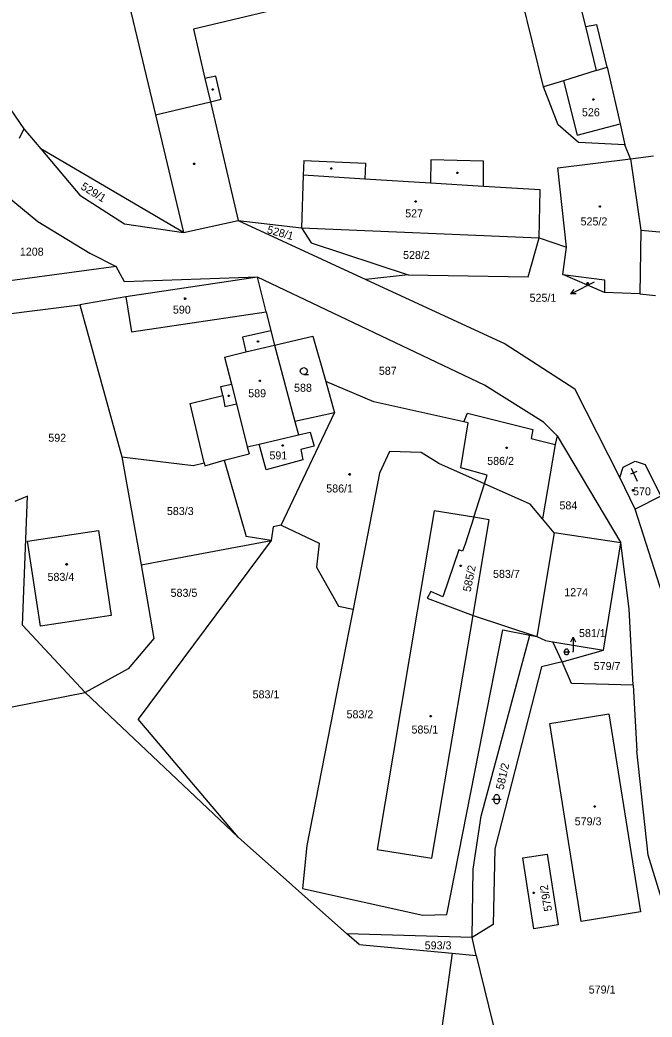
# Model space of a CAD drawing. Extents: x -812394 to -807601, y -1013097 to -1009266.
# Drawn here: x -809217.6 to -809083.2, y -1011807.5 to -1011595.7 of the extents above; entities that cross this region are included whole.
import ezdxf

# ---------------------------------------------------------------- set-up
doc = ezdxf.new("R2010")
doc.units = 0
for name, color, linetype in [('Default', 7, 'Continuous'), ('KN_HRANICE', 7, 'Continuous'), ('KN_KULTURY', 7, 'Continuous'), ('KN_PARCELY', 7, 'Continuous'), ('KN_SLUCKY', 7, 'Continuous')]:
    doc.layers.add(name, color=color, linetype=linetype)

# ---------------------------------------------------------------- blocks, each defined once
blk = doc.blocks.new('10292')
at = {"layer": 'Default'}
blk.add_line((0, 3), (0, 0), dxfattribs=at)
blk.add_lwpolyline([(-0.5, 2), (0, 3), (0.5, 2)], dxfattribs=at)
blk = doc.blocks.new('304')
at = {"layer": 'Default'}
blk.add_lwpolyline([(0, 0), (-0.38, 0.1), (-0.65, 0.37), (-0.75, 0.74), (-0.65, 1.11), (-0.38, 1.38), (-0.01, 1.48), (0.36, 1.38), (0.63, 1.11), (0.73, 0.73), (0.63, 0.35), (0.36, 0.08), (-0.02, -0.02), (0.98, -0.02)], dxfattribs=at)
blk = doc.blocks.new('316')
at = {"layer": 'Default'}
for points in [[(-1, 1), (0.27, 1), (1, 1)], [(-0.5, 1.5), (-0.4, 1.79), (-0.15, 1.97), (0.16, 1.97), (0.41, 1.79), (0.51, 1.5), (0.51, 0.5), (0.41, 0.21), (0.16, 0.03), (-0.15, 0.03), (-0.4, 0.21), (-0.5, 0.5), (-0.5, 1.5)]]:
    blk.add_lwpolyline(points, dxfattribs=at)
blk = doc.blocks.new('NAHRADNI_SYMBOL')
at = {"layer": 'Default'}
blk.add_lwpolyline([(0.09, 0.15), (0.18, 0), (0.09, -0.15), (-0.09, -0.15), (-0.18, 0), (-0.09, 0.15), (0.09, 0.15)], dxfattribs=at)
blk = doc.blocks.new('402')
at = {"layer": 'Default'}
blk.add_lwpolyline([(0.09, 0.15), (0.18, 0), (0.09, -0.15), (-0.09, -0.15), (-0.18, 0), (-0.09, 0.15), (0.09, 0.15)], dxfattribs=at)
blk = doc.blocks.new('4091')
at = {"layer": 'Default'}
for p, q in [((0, 0), (0, 3)), ((0.75, 2), (-0.75, 2))]:
    blk.add_line(p, q, dxfattribs=at)

msp = doc.modelspace()

# ---------------------------------------------------------------- linework, layer by layer
at = {"layer": 'KN_HRANICE'}
for p, q in [((-809101.83, -1011579.14), (-809097.4, -1011597.08)), ((-809195.25, -1011588.63), (-809188.78, -1011615.82)), ((-809097.4, -1011597.08), (-809094.96, -1011596.66)), ((-809097.4, -1011597.08), (-809095.09, -1011606.41)), ((-809092.74, -1011605.67), (-809094.96, -1011596.66)), ((-809095.09, -1011606.41), (-809102.07, -1011608.57)), ((-809092.74, -1011605.67), (-809090.01, -1011617.74)), ((-809102.07, -1011608.57), (-809106.29, -1011609.87)), ((-809103.15, -1011617.95), (-809106.29, -1011609.87)), ((-809221.52, -1011611.85), (-809216.75, -1011618.78)), ((-809188.78, -1011615.82), (-809182.84, -1011640.8)), ((-809216.75, -1011618.78), (-809217.74, -1011620.85)), ((-809216.75, -1011618.78), (-809213.17, -1011623.03)), ((-809098.87, -1011621.67), (-809103.15, -1011617.95)), ((-809090.01, -1011617.74), (-809089, -1011622.23)), ((-809213.17, -1011623.03), (-809204.85, -1011632.91)), ((-809182.84, -1011640.8), (-809213.17, -1011623.03)), ((-809089, -1011622.23), (-809098.87, -1011621.67)), ((-809087.79, -1011625.14), (-809089, -1011622.23)), ((-809157.25, -1011625.5), (-809157.35, -1011628.65)), ((-809157.25, -1011625.5), (-809144.15, -1011626.08)), ((-809130.23, -1011625.41), (-809130.3, -1011630.32)), ((-809119.05, -1011625.68), (-809130.23, -1011625.41)), ((-809103.23, -1011627.09), (-809087.79, -1011625.14)), ((-809087.79, -1011625.14), (-809082.89, -1011624.52)), ((-809087.79, -1011625.14), (-809085.58, -1011640.3)), ((-809144.15, -1011626.08), (-809144.3, -1011629.46)), ((-809119.05, -1011631.02), (-809119.05, -1011625.68)), ((-809101.39, -1011643.91), (-809103.23, -1011627.09)), ((-809157.35, -1011628.65), (-809157.72, -1011639.81)), ((-809130.3, -1011630.32), (-809144.3, -1011629.46)), ((-809107.02, -1011631.76), (-809119.05, -1011631.02)), ((-809107.24, -1011641.99), (-809107.02, -1011631.76)), ((-809220.29, -1011633.09), (-809213.78, -1011638.47)), ((-809204.85, -1011632.91), (-809195.39, -1011638.95)), ((-809213.78, -1011638.47), (-809202.74, -1011645.23)), ((-809195.39, -1011638.95), (-809182.84, -1011640.8)), ((-809182.84, -1011640.8), (-809171.23, -1011638.28)), ((-809171.23, -1011638.28), (-809144.03, -1011650.78)), ((-809171.23, -1011638.28), (-809157.72, -1011639.81)), ((-809157.72, -1011639.81), (-809107.24, -1011641.99)), ((-809157.72, -1011639.81), (-809155.66, -1011643.03)), ((-809085.58, -1011640.3), (-809085.85, -1011653.87)), ((-809085.58, -1011640.3), (-809061.33, -1011642.55)), ((-809109.56, -1011650.26), (-809107.24, -1011641.99)), ((-809107.24, -1011641.99), (-809101.39, -1011643.91)), ((-809155.66, -1011643.03), (-809135.05, -1011649.8)), ((-809102.17, -1011649.74), (-809101.39, -1011643.91)), ((-809202.74, -1011645.23), (-809197.11, -1011648.02)), ((-809197.11, -1011648.02), (-809233.77, -1011652.99)), ((-809195.36, -1011651.32), (-809197.11, -1011648.02)), ((-809167.11, -1011650.32), (-809195.36, -1011651.32)), ((-809167.11, -1011650.32), (-809195.04, -1011654.47)), ((-809165.24, -1011657.69), (-809167.11, -1011650.32)), ((-809118.81, -1011673.24), (-809167.11, -1011650.32)), ((-809135.05, -1011649.8), (-809144.03, -1011650.78)), ((-809144.03, -1011650.78), (-809114.47, -1011664.51)), ((-809135.05, -1011649.8), (-809109.56, -1011650.26)), ((-809093.35, -1011653.56), (-809102.17, -1011649.74)), ((-809102.17, -1011649.74), (-809093.31, -1011650.88)), ((-809093.31, -1011650.88), (-809093.35, -1011653.56)), ((-809195.04, -1011654.47), (-809204.84, -1011656.21)), ((-809085.85, -1011653.87), (-809093.35, -1011653.56)), ((-809085.85, -1011653.87), (-809082.52, -1011654.22)), ((-809221.7, -1011658.29), (-809204.84, -1011656.21)), ((-809204.84, -1011656.21), (-809195.9, -1011688.5)), ((-809165.24, -1011657.69), (-809164.26, -1011661.71)), ((-809164.26, -1011661.71), (-809170.27, -1011663.04)), ((-809170.27, -1011663.04), (-809169.57, -1011666.21)), ((-809164.26, -1011661.71), (-809163.49, -1011664.76)), ((-809163.49, -1011664.76), (-809155.36, -1011662.84)), ((-809155.36, -1011662.84), (-809152.6, -1011672.5)), ((-809163.49, -1011664.76), (-809159.14, -1011680.97)), ((-809114.47, -1011664.51), (-809099.63, -1011674.03)), ((-809174.08, -1011667.28), (-809169.57, -1011666.21)), ((-809174.08, -1011667.28), (-809172.62, -1011673.04)), ((-809174.88, -1011673.53), (-809172.62, -1011673.04)), ((-809174.49, -1011675.49), (-809174.88, -1011673.53)), ((-809142.39, -1011676.83), (-809152.6, -1011672.5)), ((-809152.6, -1011672.5), (-809150.71, -1011679.14)), ((-809106.3, -1011681.14), (-809118.81, -1011673.24)), ((-809090.09, -1011692.88), (-809099.63, -1011674.03)), ((-809181.41, -1011677.14), (-809174.49, -1011675.49)), ((-809178.41, -1011689.79), (-809181.41, -1011677.14)), ((-809123.26, -1011681.02), (-809142.39, -1011676.83)), ((-809162.04, -1011703.02), (-809150.71, -1011679.14)), ((-809150.71, -1011679.14), (-809159.14, -1011680.97)), ((-809123.26, -1011681.02), (-809122.44, -1011679.19)), ((-809122.44, -1011679.19), (-809108.6, -1011682.65)), ((-809159.14, -1011680.97), (-809158.38, -1011683.82)), ((-809123.9, -1011690.84), (-809122.31, -1011681.23)), ((-809122.31, -1011681.23), (-809123.26, -1011681.02)), ((-809108.6, -1011682.65), (-809108.92, -1011684.62)), ((-809103.4, -1011684.01), (-809106.3, -1011681.14)), ((-809166.74, -1011685.77), (-809158.38, -1011683.82)), ((-809108.92, -1011684.62), (-809103.84, -1011685.87)), ((-809103.4, -1011684.01), (-809103.84, -1011685.87)), ((-809103.4, -1011684.01), (-809089.88, -1011706.73)), ((-809169.26, -1011686.36), (-809166.74, -1011685.77)), ((-809169.26, -1011686.36), (-809168.89, -1011687.82)), ((-809103.84, -1011685.87), (-809106.54, -1011701.66)), ((-809195.9, -1011688.5), (-809180.76, -1011690.33)), ((-809195.9, -1011688.5), (-809191.85, -1011711.45)), ((-809174.17, -1011689.22), (-809168.89, -1011687.82)), ((-809139.05, -1011687.35), (-809141.13, -1011691.93)), ((-809132.32, -1011687.55), (-809139.05, -1011687.35)), ((-809128.57, -1011689.88), (-809132.32, -1011687.55)), ((-809180.76, -1011690.33), (-809178.41, -1011689.79)), ((-809178.41, -1011689.79), (-809178.26, -1011690.42)), ((-809178.26, -1011690.42), (-809174.17, -1011689.22)), ((-809174.17, -1011689.22), (-809169.49, -1011705.38)), ((-809118.86, -1011694.22), (-809128.57, -1011689.88)), ((-809118.27, -1011692.36), (-809123.9, -1011690.84)), ((-809090.09, -1011692.88), (-809089.34, -1011690.67)), ((-809089.34, -1011690.67), (-809086.85, -1011689.4)), ((-809086.85, -1011689.4), (-809084.66, -1011690.15)), ((-809084.66, -1011690.15), (-809081.39, -1011696.85)), ((-809141.13, -1011691.93), (-809146.78, -1011720.87)), ((-809118.86, -1011694.22), (-809118.27, -1011692.36)), ((-809086.82, -1011699.58), (-809090.09, -1011692.88)), ((-809121.11, -1011701.32), (-809118.86, -1011694.22)), ((-809109.13, -1011698.56), (-809118.86, -1011694.22)), ((-809215.97, -1011696.83), (-809218.66, -1011698.01)), ((-809217.07, -1011724.24), (-809215.97, -1011696.83)), ((-809081.39, -1011696.85), (-809086.82, -1011699.58)), ((-809106.54, -1011701.66), (-809109.13, -1011698.56)), ((-809079.24, -1011723.27), (-809086.82, -1011699.58)), ((-809129.54, -1011699.97), (-809133.14, -1011721.27)), ((-809121.11, -1011701.32), (-809129.54, -1011699.97)), ((-809121.11, -1011701.32), (-809122.92, -1011707.03)), ((-809117.84, -1011701.84), (-809121.11, -1011701.32)), ((-809104.04, -1011704.66), (-809106.54, -1011701.66)), ((-809163.75, -1011703.34), (-809164.16, -1011706.25)), ((-809162.04, -1011703.02), (-809163.75, -1011703.34)), ((-809162.04, -1011703.02), (-809154.01, -1011706.83)), ((-809121.28, -1011722.18), (-809117.84, -1011701.84)), ((-809215.97, -1011706.41), (-809200.9, -1011704.12)), ((-809200.9, -1011704.12), (-809198.16, -1011722.17)), ((-809164.16, -1011706.25), (-809169.49, -1011705.38)), ((-809104.04, -1011704.66), (-809107.75, -1011726.64)), ((-809089.88, -1011706.73), (-809104.04, -1011704.66)), ((-809213.22, -1011724.44), (-809215.97, -1011706.41)), ((-809164.16, -1011706.25), (-809192.44, -1011744.19)), ((-809191.85, -1011711.45), (-809164.16, -1011706.25)), ((-809154.01, -1011706.83), (-809154.57, -1011711.95)), ((-809122.92, -1011707.03), (-809123.54, -1011708.51)), ((-809093.54, -1011729.56), (-809089.88, -1011706.73)), ((-809088.11, -1011720.75), (-809089.88, -1011706.73)), ((-809124.3, -1011708.21), (-809127.72, -1011718.26)), ((-809123.54, -1011708.51), (-809124.3, -1011708.21)), ((-809191.85, -1011711.45), (-809189.09, -1011727.11)), ((-809154.57, -1011711.95), (-809149.9, -1011720.22)), ((-809130.26, -1011717.12), (-809131.05, -1011718.48)), ((-809131.05, -1011718.48), (-809121.28, -1011722.18)), ((-809127.72, -1011718.26), (-809130.26, -1011717.12)), ((-809149.9, -1011720.22), (-809146.78, -1011720.87)), ((-809146.78, -1011720.87), (-809147.74, -1011725.8)), ((-809087.23, -1011736.98), (-809088.11, -1011720.75)), ((-809198.16, -1011722.17), (-809213.22, -1011724.44)), ((-809133.14, -1011721.27), (-809141.69, -1011771.9)), ((-809130.02, -1011773.75), (-809121.28, -1011722.18)), ((-809121.28, -1011722.18), (-809107.75, -1011726.64)), ((-809217.07, -1011724.24), (-809203.75, -1011738.59)), ((-809189.09, -1011727.11), (-809194.56, -1011733.56)), ((-809147.74, -1011725.8), (-809156.57, -1011771.05)), ((-809126.88, -1011785.75), (-809114.95, -1011725.23)), ((-809119.53, -1011764.8), (-809109.23, -1011726.35)), ((-809114.95, -1011725.23), (-809109.23, -1011726.35)), ((-809109.23, -1011726.35), (-809107.75, -1011726.64)), ((-809107.75, -1011726.64), (-809105.87, -1011727.54)), ((-809105.87, -1011727.54), (-809104.33, -1011727.8)), ((-809102.34, -1011732.05), (-809104.33, -1011727.8)), ((-809104.33, -1011727.8), (-809093.54, -1011729.56)), ((-809102.34, -1011732.05), (-809093.54, -1011729.56)), ((-809194.56, -1011733.56), (-809203.75, -1011738.59)), ((-809106.72, -1011733.12), (-809116.67, -1011771.8)), ((-809102.34, -1011732.05), (-809106.72, -1011733.12)), ((-809100.36, -1011736.65), (-809102.34, -1011732.05)), ((-809087.23, -1011736.98), (-809100.36, -1011736.65)), ((-809087.23, -1011736.98), (-809086.47, -1011750.97)), ((-809219.25, -1011741.58), (-809203.75, -1011738.59)), ((-809203.75, -1011738.59), (-809171.21, -1011769.31)), ((-809104.96, -1011745.11), (-809092.42, -1011743.1)), ((-809092.42, -1011743.1), (-809085.69, -1011785.15)), ((-809171.21, -1011769.31), (-809192.44, -1011744.19)), ((-809098.28, -1011787.19), (-809104.96, -1011745.11)), ((-809084.06, -1011773.13), (-809086.47, -1011750.97)), ((-809121.22, -1011776.06), (-809119.53, -1011764.8)), ((-809148.1, -1011789.81), (-809171.21, -1011769.31)), ((-809156.57, -1011771.05), (-809157.53, -1011780.19)), ((-809141.69, -1011771.9), (-809130.02, -1011773.75)), ((-809116.67, -1011771.8), (-809116.97, -1011787.86)), ((-809110.7, -1011773.71), (-809105.55, -1011772.9)), ((-809108.37, -1011788.76), (-809110.7, -1011773.71)), ((-809105.55, -1011772.9), (-809103.18, -1011787.93)), ((-809068.2, -1011824.99), (-809084.06, -1011773.13)), ((-809121.45, -1011790.63), (-809121.22, -1011776.06)), ((-809157.53, -1011780.19), (-809131.97, -1011785.87)), ((-809131.97, -1011785.87), (-809126.88, -1011785.75)), ((-809085.69, -1011785.15), (-809098.28, -1011787.19)), ((-809116.97, -1011787.86), (-809121.45, -1011790.63)), ((-809103.18, -1011787.93), (-809108.37, -1011788.76)), ((-809121.45, -1011790.63), (-809148.1, -1011789.81)), ((-809145.51, -1011792.11), (-809148.1, -1011789.81)), ((-809120.59, -1011794.42), (-809121.45, -1011790.63)), ((-809145.51, -1011792.11), (-809125.69, -1011793.95)), ((-809125.69, -1011793.95), (-809130.74, -1011830.07)), ((-809125.69, -1011793.95), (-809120.59, -1011794.42)), ((-809120.59, -1011794.42), (-809112.8, -1011826.22))]:
    msp.add_line(p, q, dxfattribs=at)
at = {"layer": 'KN_PARCELY'}
for p, q in [((-809095.51, -1011651.38), (-809097.8, -1011652.51)), ((-809100, -1011729.97), (-809100, -1011729.78))]:
    msp.add_line(p, q, dxfattribs=at)
at = {"layer": 'KN_SLUCKY'}
for p, q in [((-809106.29, -1011609.87), (-809113.22, -1011581.56)), ((-809152.89, -1011590.98), (-809180.72, -1011597.59)), ((-809180.72, -1011597.59), (-809178.26, -1011608.13)), ((-809095.09, -1011606.41), (-809092.74, -1011605.67)), ((-809175.97, -1011607.59), (-809178.26, -1011608.13)), ((-809178.26, -1011608.13), (-809177.11, -1011613.05)), ((-809174.8, -1011612.5), (-809175.97, -1011607.59)), ((-809102.07, -1011608.57), (-809099.14, -1011620.13)), ((-809177.11, -1011613.05), (-809174.8, -1011612.5)), ((-809188.78, -1011615.82), (-809177.11, -1011613.05)), ((-809177.11, -1011613.05), (-809171.23, -1011638.28)), ((-809099.14, -1011620.13), (-809090.01, -1011617.74)), ((-809144.3, -1011629.46), (-809157.35, -1011628.65)), ((-809119.05, -1011631.02), (-809130.3, -1011630.32)), ((-809195.04, -1011654.47), (-809193.85, -1011661.92)), ((-809193.85, -1011661.92), (-809165.24, -1011657.69)), ((-809169.57, -1011666.21), (-809163.49, -1011664.76)), ((-809172.62, -1011673.04), (-809171.56, -1011677.23)), ((-809174.49, -1011675.49), (-809174.02, -1011677.78)), ((-809174.02, -1011677.78), (-809171.56, -1011677.23)), ((-809171.56, -1011677.23), (-809169.26, -1011686.36)), ((-809158.38, -1011683.82), (-809155.87, -1011683.24)), ((-809155.87, -1011683.24), (-809155.08, -1011686.23)), ((-809165.28, -1011691.23), (-809166.74, -1011685.77)), ((-809155.08, -1011686.23), (-809157.86, -1011686.96)), ((-809157.86, -1011686.96), (-809157.43, -1011689.13)), ((-809157.43, -1011689.13), (-809165.28, -1011691.23))]:
    msp.add_line(p, q, dxfattribs=at)

# ---------------------------------------------------------------- block references
at = {"layer": 'KN_KULTURY'}
for name, p in [('402', (-809176.6, -1011610.42)), ('402', (-809095.68, -1011612.58)), ('402', (-809180.55, -1011626.23)), ('402', (-809151.42, -1011627.22)), ('402', (-809124.59, -1011628.14)), ('402', (-809133.48, -1011634.23)), ('NAHRADNI_SYMBOL', (-809094.32, -1011635.28)), ('NAHRADNI_SYMBOL', (-809096.92, -1011651.62)), ('402', (-809182.47, -1011654.89)), ('402', (-809166.99, -1011663.96)), ('304', (-809157.25, -1011671)), ('402', (-809166.59, -1011672.32)), ('402', (-809173.19, -1011675.51)), ('402', (-809161.73, -1011686.1)), ('NAHRADNI_SYMBOL', (-809114.12, -1011686.56)), ('NAHRADNI_SYMBOL', (-809147.53, -1011692.2)), ('402', (-809087.25, -1011695.61)), ('402', (-809207.64, -1011711.32)), ('402', (-809123.9, -1011711.64)), ('402', (-809130.29, -1011743.58)), ('316', (-809116.27, -1011762.23)), ('402', (-809095.4, -1011762.79)), ('402', (-809108.37, -1011781.14))]:
    msp.add_blockref(name, p, dxfattribs=at)
at = {"layer": 'KN_KULTURY', "rotation": 24.178819}
msp.add_blockref('4091', (-809086.34, -1011693.71), dxfattribs=at)
at = {"layer": 'KN_KULTURY', "xscale": 0.67, "yscale": 0.67}
msp.add_blockref('316', (-809101.4, -1011730.59), dxfattribs=at)
at = {"layer": 'KN_PARCELY', "rotation": 116.31043199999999}
msp.add_blockref('10292', (-809097.8, -1011652.51), dxfattribs=at)
at = {"layer": 'KN_PARCELY'}
msp.add_blockref('10292', (-809100, -1011729.78), dxfattribs=at)

# ---------------------------------------------------------------- texts
for s, height, p in [('526', 1.7, (-809098.13, -1011616.13)), ('527', 1.7, (-809135.7, -1011637.61)), ('525/2', 1.7, (-809098.42, -1011639.32)), ('1208', 1.7, (-809217.6, -1011645.75)), ('528/2', 1.7, (-809136.15, -1011646.45)), ('525/1', 0.1, (-809095.74, -1011651.38)), ('525/1', 1.7, (-809109.26, -1011655.54)), ('590', 1.7, (-809185.07, -1011658.06)), ('587', 1.7, (-809141.3, -1011671.06)), ('589', 1.7, (-809169.06, -1011675.83)), ('588', 1.7, (-809159.32, -1011674.66)), ('592', 1.7, (-809211.55, -1011685.28)), ('591', 1.7, (-809164.55, -1011689.03)), ('586/2', 1.7, (-809118.27, -1011690.2)), ('586/1', 1.7, (-809152.48, -1011696.06)), ('570', 1.7, (-809087.27, -1011696.66)), ('583/3', 1.7, (-809186.35, -1011700.85)), ('584', 1.7, (-809102.91, -1011699.65)), ('583/4', 1.7, (-809211.72, -1011714.84)), ('583/7', 1.7, (-809117.03, -1011714.2)), ('583/5', 1.7, (-809185.56, -1011718.23)), ('1274', 1.7, (-809101.88, -1011718.09)), ('581/1', 1.7, (-809098.76, -1011726.78)), ('579/7', 1.7, (-809095.63, -1011733.78)), ('583/1', 1.7, (-809168.13, -1011739.79)), ('583/2', 1.7, (-809148.16, -1011744.03)), ('585/1', 1.7, (-809134.36, -1011747.27)), ('579/3', 1.7, (-809099.67, -1011766.78)), ('593/3', 1.7, (-809131.55, -1011793.13)), ('579/1', 1.7, (-809096.69, -1011802.51))]:
    msp.add_text(s, height=height, dxfattribs=at).set_placement(p)
for s, height, rotation, p in [('529/1', 1.7, 328.362, (-809204.81, -1011631.49)), ('528/1', 1.7, 344.29, (-809165.19, -1011640.93)), ('585/2', 1.7, 78.495, (-809121.8, -1011717.27)), ('581/1', 0.1, 351.223, (-809100.23, -1011729.94)), ('581/2', 1.7, 77.521, (-809114.8, -1011759.31)), ('579/2', 1.7, 99.924, (-809104.46, -1011784.89))]:
    msp.add_text(s, height=height, rotation=rotation, dxfattribs=at).set_placement(p)

doc.saveas('drawing.dxf')
